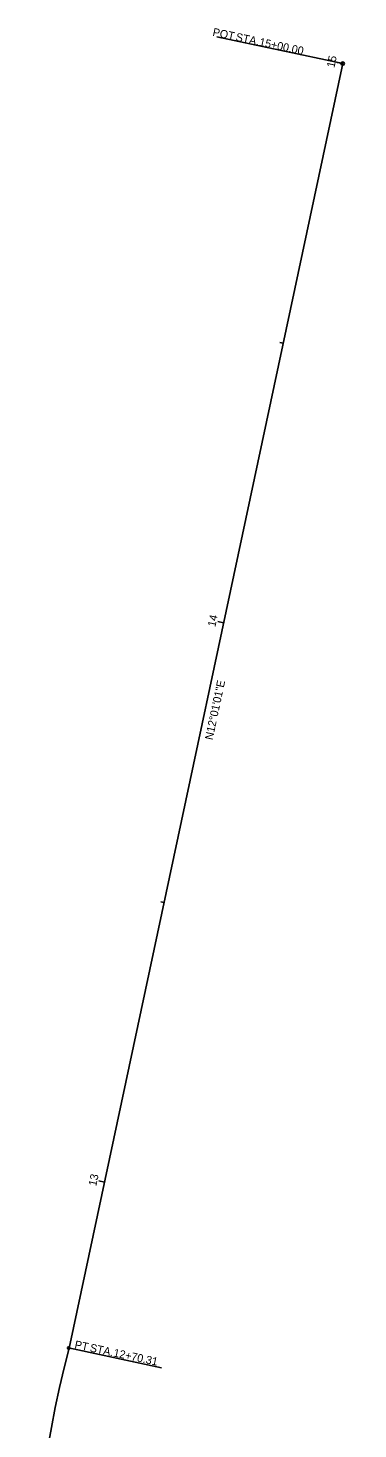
# Model space of a CAD drawing. Extents: x 2296409 to 2296500, y 654819 to 655309.
# Drawn here: x 2296411.1 to 2296468.7, y 655064.1 to 655309.1 of the extents above; entities that cross this region are included whole.
import ezdxf

# ---------------------------------------------------------------- set-up
doc = ezdxf.new("R2010")
doc.units = 0
for name, color, linetype in [('Default', 7, 'Continuous'), ('GE_P_Alignment', 7, 'Continuous'), ('GE_P_Alignment_100_Bearings', 7, 'Continuous'), ('GE_P_Alignment_100_Cardinal_Points', 7, 'Continuous'), ('GE_P_Alignment_100_Stations', 7, 'Continuous')]:
    doc.layers.add(name, color=color, linetype=linetype)

msp = doc.modelspace()

# ---------------------------------------------------------------- linework, layer by layer
at = {"layer": 'Default'}
for p, q in [((2296422.51, 655098.16), (2296422.51, 655098.2)), ((2296422.51, 655098.2), (2296422.51, 655098.19))]:
    msp.add_line(p, q, dxfattribs=at)
at = {"layer": 'GE_P_Alignment'}
msp.add_line((2296418.26, 655078.22), (2296466.08, 655302.88), dxfattribs=at)
msp.add_line((2296418.26, 655078.22), (2296466.08, 655302.88), dxfattribs=at)
msp.add_arc((2296640.37, 655021.32), 229.28, 165.6301, 221.5381, dxfattribs=at)
msp.add_arc((2296640.37, 655021.32), 229.28, 165.6301, 221.5381, dxfattribs=at)
at = {"layer": 'GE_P_Alignment_100_Cardinal_Points'}
for p, q in [((2296466.08, 655302.88), (2296444.08, 655307.56)), ((2296418.18, 655078.24), (2296434.39, 655074.79))]:
    msp.add_line(p, q, dxfattribs=at)
for centre, radius in [((2296466.08, 655302.88), 0.3), ((2296418.18, 655078.24), 0.221)]:
    msp.add_circle(centre, radius, dxfattribs=at)
at = {"layer": 'GE_P_Alignment_100_Stations'}
for p, q in [((2296466.08, 655302.88), (2296465.1, 655303.09)), ((2296455.67, 655253.97), (2296455.09, 655254.1)), ((2296445.26, 655205.07), (2296444.28, 655205.28)), ((2296434.85, 655156.17), (2296434.27, 655156.29)), ((2296424.44, 655107.26), (2296423.46, 655107.47))]:
    msp.add_line(p, q, dxfattribs=at)

# ---------------------------------------------------------------- texts
at = {"layer": 'GE_P_Alignment_100_Bearings'}
msp.add_text('N12°01\'01"E', height=1.4, rotation=77.983, dxfattribs=at).set_placement((2296443.34, 655184.49))
at = {"layer": 'GE_P_Alignment_100_Cardinal_Points'}
for s, p in [('POT', (2296443.26, 655307.76)), (' STA. ', (2296446.78, 655307.01)), ('15+00.00', (2296451.4, 655306.02)), ('PT', (2296419.13, 655078.21)), (' STA. ', (2296421.29, 655077.75)), ('12+70.31', (2296425.92, 655076.77))]:
    msp.add_text(s, height=1.4, rotation=347.983, dxfattribs=at).set_placement(p)
at = {"layer": 'GE_P_Alignment_100_Stations'}
for s, p in [('15', (2296464.63, 655302.07)), ('14', (2296443.82, 655204.28)), ('13', (2296423, 655106.47))]:
    msp.add_text(s, height=1.4, rotation=77.983, dxfattribs=at).set_placement(p)

doc.saveas('drawing.dxf')
